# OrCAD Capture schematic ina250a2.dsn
size A; title: INA293 40-V High-Voltage, High Bandwidth, Unidirectional, 110-V Common-Mode Current-Sense Amplifier; rev: A; note: SBOS870
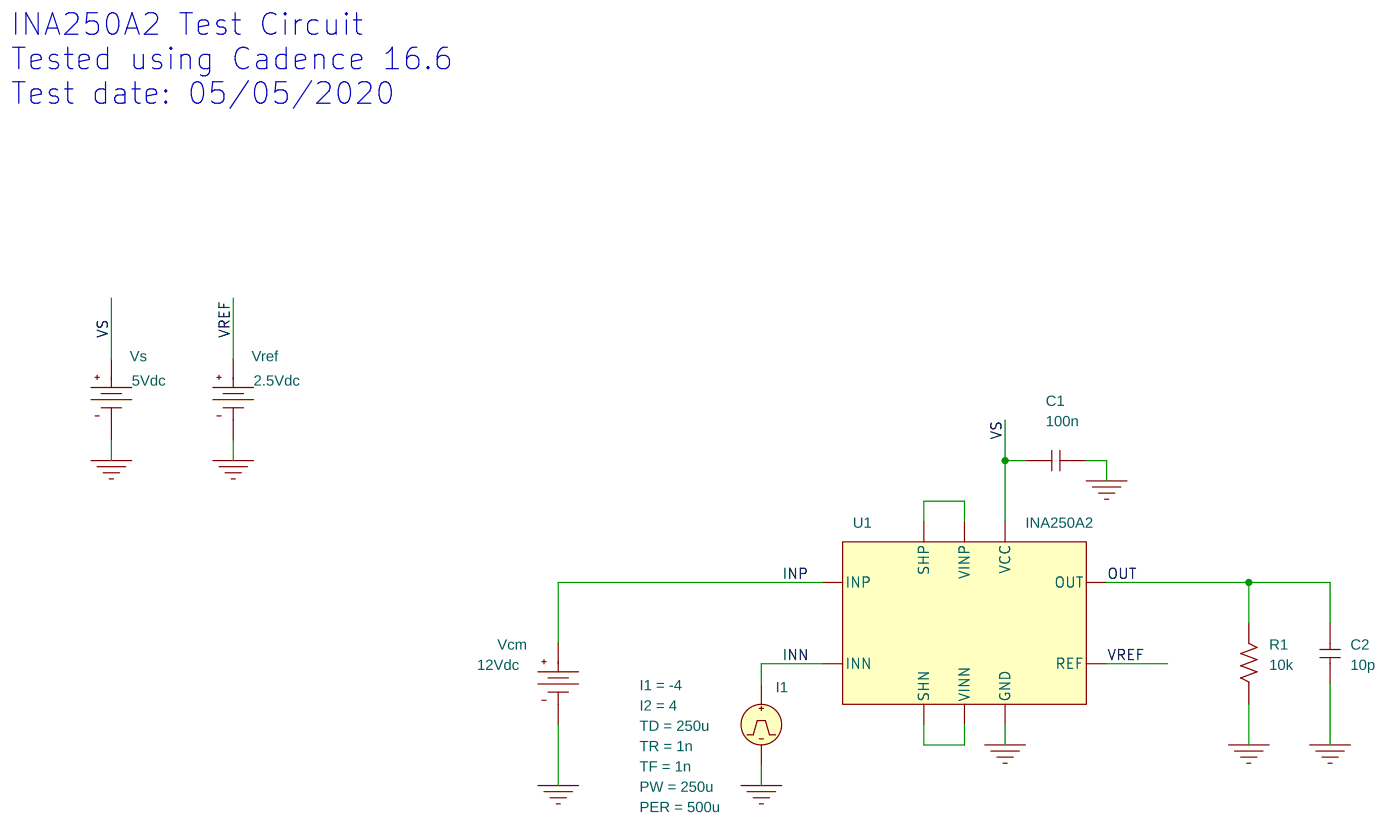
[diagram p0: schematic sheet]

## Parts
C1  100n  [RAD/CK05]
C2  10p  [RAD/CK05]
I1  IPULSE
R1  10k  [AX/RC05]
U1  INA250A2
Vcm  VDC
Vref  VDC
Vs  VDC

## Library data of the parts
C1 C2 = C
I1 = IPULSE: I1: -4; I2: 4; PER: 500u; PW: 250u; TD: 250u; TF: 1n; TR: 1n
R1 = R
U1 = INA250A2
Vcm = VDC: DC: 12Vdc
Vref = VDC: DC: 2.5Vdc
Vs = VDC: DC: 5Vdc

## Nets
0: C1.1 C2.1 I1.2(-) R1.1 U1.GND Vcm.1(-) Vref.1(-) Vs.1(-)
INN: I1.1(+) U1.INN
INP: U1.INP Vcm.0(+)
OUT: C2.2 R1.2 U1.OUT
VREF: U1.REF Vref.0(+)
VS: C1.2 U1.VCC Vs.0(+)
N24993: U1.SHP U1.VINP
N25005: U1.SHN U1.VINN

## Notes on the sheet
- INA250A2 Test Circuit
  Tested using Cadence 16.6
  Test date: 05/05/2020
